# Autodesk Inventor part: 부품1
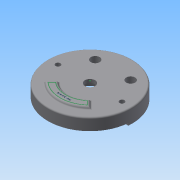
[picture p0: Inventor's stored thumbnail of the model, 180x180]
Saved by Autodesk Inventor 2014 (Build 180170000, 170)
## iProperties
Created: 2015-04
Part Number: 부품1
Material: Generic
Document SubType Name: Modeling
Designer: Administrator
Density: 1 g/cm^3
Appearance: Default
Author: Administrator
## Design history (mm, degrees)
sketch "스케치2"
  geometry: C1 r 95 at (0, 0); 1 further point
  constraints: 1 centre point, 1 coincident
  dimensions: "d0" = 190 diameter of C1
extrude "돌출1" new body sketch "스케치2" distance "d1" = 27; taper "d2" = 0 deg
feature "쉘2" dims "d4" = 13
sketch "스케치7"
  geometry: L1 (0, 0)-(94.712, -8.286); L2 (0, 0)-(-94.712, -8.286); A1 r 95 centre (0, 0) between (94.638, -8.28) and (-94.638, -8.28); A2 r 82 centre (0, 0) between (81.688, -7.147) and (-81.688, -7.147)
  constraints: 4 end point, 4 point on circle, 4 point on line, 2 centre point, 2 coincident
  dimensions: "d7" = 190 diameter of A1; "d8" = 164 diameter of A2
extrude "돌출2" join sketch "스케치7" distance "d9" = 5; taper "d10" = 0 deg
sketch "스케치11"
  geometry: C1 r 82 at (0, 0) reference; C2 r 35 at (0, 0)
  constraints: 1 centre point, 1 coincident
  dimensions: "d16" = 70 diameter of C2
extrude "돌출3" join sketch "스케치11" distance "d17" = 10; taper "d18" = 0 deg
sketch "스케치12"
  geometry: C1 r 35 at (0, 0) reference; C2 r 25 at (0, 0)
  constraints: 1 centre point, 1 coincident
  dimensions: "d19" = 50 diameter of C2
extrude "돌출4" cut sketch "스케치12" distance "d20" = 15; taper "d21" = 0 deg
sketch "스케치13"
  geometry: C1 r 95 at (0, 0) reference; C2 r 11.5 at (0, 0)
  constraints: 1 centre point, 1 coincident
  dimensions: "d22" = 23 diameter of C2
extrude "돌출5" cut sketch "스케치13" stored distance "d23" = 15; taper "d24" = 0 deg
feature "면 기울기1" dims angle "d26" = 2.5 deg
fillet "모깎기2" dims "d27" = 3
sketch "스케치14"
  geometry: L1 (94.638, -8.28)-(81.688, -7.147) reference; L2 (-81.117, 12)-(-40.249, 12); L3 (40.249, 12)-(81.117, 12); A1 r 42 centre (0, 0) between (40.249, 12) and (-40.249, 12); A2 r 82 centre (0, 0) between (81.117, 12) and (-81.117, 12)
  constraints: 5 end point, 4 point on circle, 2 centre point, 2 coincident
extrude "돌출6" cut sketch "스케치14" distance "d31" = 25; taper "d32" = 0 deg
sketch "스케치15"
  geometry: C1 r 15 at (-40, 52); C2 r 15 at (40, 52); A1 r 42 centre (0, 0) between (40.249, 12) and (-40.249, 12) reference
  constraints: 2 centre point
  dimensions: "d35" = 30 diameter of C1; "d36" = 30 diameter of C2; "d37" = 52 vertical distance of A1.centre C2.centre; "d38" = 52 vertical distance of A1.centre C1.centre; "d39" = 80 distance of C2.centre C1.centre
extrude "돌출7" join sketch "스케치15" stored distance "d40" = 25; taper "d41" = 0 deg
sketch "스케치16"
  geometry: L1 (-6, 15.792)-(6, 15.792); L2 (6, 15.792)-(6, -15.792); L3 (6, -15.792)-(-6, -15.792); L4 (-6, -15.792)-(-6, 15.792); L5 (97.394, -6)-(62.606, -6); L6 (62.606, -6)-(62.606, 6); L7 (62.606, 6)-(97.394, 6); L8 (97.394, 6)-(97.394, -6); C1 r 15 at (0, 0) reference; C2 r 15 at (80, 0) reference; 5 further points
  constraints: 16 end point, 4 midpoint, 4 parallel, 2 horizontal, 2 horizontal alignment, 2 perpendicular, 2 vertical alignment
  dimensions: "d42" = 12 distance of L1.start L1.end; "d43" = 31.58445 distance between parallel lines of L3 L1; "d48" = 12 distance of L5.end L6.end; "d49" = 34.78796 distance of L6.end L7.end
extrude "돌출8" cut sketch "스케치16" distance "d46" = 3; taper "d47" = 0 deg
sketch "스케치17"
  geometry: L1 (66.252, 6)-(93.748, 6) reference; C1 r 10 at (0, 0); C2 r 10 at (80, 0); A1 r 15 centre (0, 0) between (6, -13.748) and (6, 13.748) reference; A2 r 15 centre (80, 0) between (93.748, 6) and (66.252, 6) reference; 1 further point
  constraints: 2 centre point, 2 coincident
  dimensions: "d50" = 20 diameter of C1; "d51" = 20 diameter of C2
extrude "돌출9" cut sketch "스케치17" stored distance "d52" = 3; taper "d53" = 0 deg
sketch "스케치18" dims "d54" = 145
  geometry: L1 (81.117, 12)-(40.249, 12) reference; L2 (0, 0)-(-132.17, 0); C1 r 38.308 at (0, 0) reference; C2 r 9 at (-72.5, 0)
  constraints: 2 end point, 1 centre point, 1 coincident, 1 horizontal alignment, 1 parallel, 1 point on line, 2 other
  dimensions: "d55" = 18 diameter of C2
extrude "돌출10" join sketch "스케치18" stored distance "d57" = 3; taper "d58" = 0 deg
sketch "스케치19"
  geometry: C1 r 9 at (0, 0) reference; C2 r 5.5 at (0, 0); 1 further point
  constraints: 1 centre point, 1 coincident
  dimensions: "d59" = 11 diameter of C2
extrude "돌출11" cut sketch "스케치19" stored distance "d60" = 3; taper "d61" = 0 deg
sketch "스케치20"
  geometry: L1 (-40.249, 12)-(-81.117, 12) reference; L2 (81.117, 12)-(40.249, 12) reference; C1 r 9 at (72.5, 0) reference; C2 r 9 at (-72.5, 0) reference; C3 r 38.308 at (0, 0) reference; A1 r 82 centre (0, 0) between (-81.117, 12) and (81.117, 12) reference; A2 r 42 centre (0, 0) between (40.249, 12) and (-40.249, 12) reference
sketch "스케치21"
  geometry: L1 (-40.249, 12)-(-81.117, 12) reference; L2 (0, 0)-(-105.129, 0); L3 (-40.694, -14)-(-58.788, -14); L4 (0, 0)-(0, -103.974); A1 r 82 centre (0, 0) between (-81.117, 12) and (81.117, 12) reference; A2 r 9.047 centre (-49.741, -14) between (-40.875, -15.801) and (-58.788, -14); A3 r 9.047 centre (49.741, -14) between (58.788, -14) and (40.875, -15.801); A4 r 41 centre (0, -19) between (-40.694, -14) and (40.694, -14); A5 r 41 centre (0, -19) between (-36.332, 0) and (-38.111, -3.883); A6 r 59 centre (0, -19) between (-58.607, -12.199) and (58.607, -12.199)
  constraints: 18 point on circle, 6 end point, 5 centre point, 2 parallel, 1 coincident, 1 midpoint, 1 perpendicular, 1 point on line, 1 symmetric about line, 1 vertical alignment, 3 other
  dimensions: "d62" = 19 distance of A1.centre A6.centre; "d66" = 18.09377 diameter of A2; "d67" = 59 radius of A6; "d68" = 41 radius of A4
extrude "돌출12" cut sketch "스케치21" distance "d69" = 7; taper "d70" = 0 deg
fillet "모깎기3" dims "d71" = 1, "d72" = 3
fillet "모깎기4" dims "d73" = 3
sketch "스케치22"
  geometry: L1 (0, 0)-(0, -99.453); L2 (-36.062, -36.062)-(-50.912, -50.912); L3 (36.062, -36.062)-(50.912, -50.912); C1 r 92 at (0, 0) reference; A1 r 72 centre (0, 0) between (-50.912, -50.912) and (50.912, -50.912); A2 r 51 centre (0, 0) between (-36.062, -36.062) and (36.062, -36.062)
  constraints: 6 end point, 4 point on circle, 2 centre point, 2 coincident, 1 vertical
  dimensions: "d74" = 144 diameter of A1; "d75" = 102 diameter of A2; "d78" = 45 deg angle of L1 L3; "d79" = 45 deg angle of L2 L1; "d80" = 101.82338 distance of L3.end L2.end; "d81" = 21 distance of L2.start L2.end
extrude "돌출13" join sketch "스케치22" distance "d82" = 5; taper "d83" = 0 deg
fillet "모깎기5" dims "d84" = 3, "d85" = 5
sketch "스케치25"
  geometry: L1 (35.938, -42.183)-(44.564, -50.81) reference; L2 (-44.564, -50.81)-(-35.938, -42.183) reference; L3 (-16.86, -58.424)-(20.74, -58.424); L4 (20.74, -58.424)-(20.74, -62.895); L5 (20.74, -62.895)-(-16.86, -62.895); L6 (-16.86, -62.895)-(-16.86, -58.424); 1 further point
  constraints: 2 horizontal alignment, 2 other
node "솔리드1"
mirror "대칭1"
mirror "대칭2"
node "투영된 루프1"
other parameters: "d29" = 164, "d63" = 118, "d64" = 82, "d65" = 14, "d76" = 45 deg, "d77" = 45 deg
